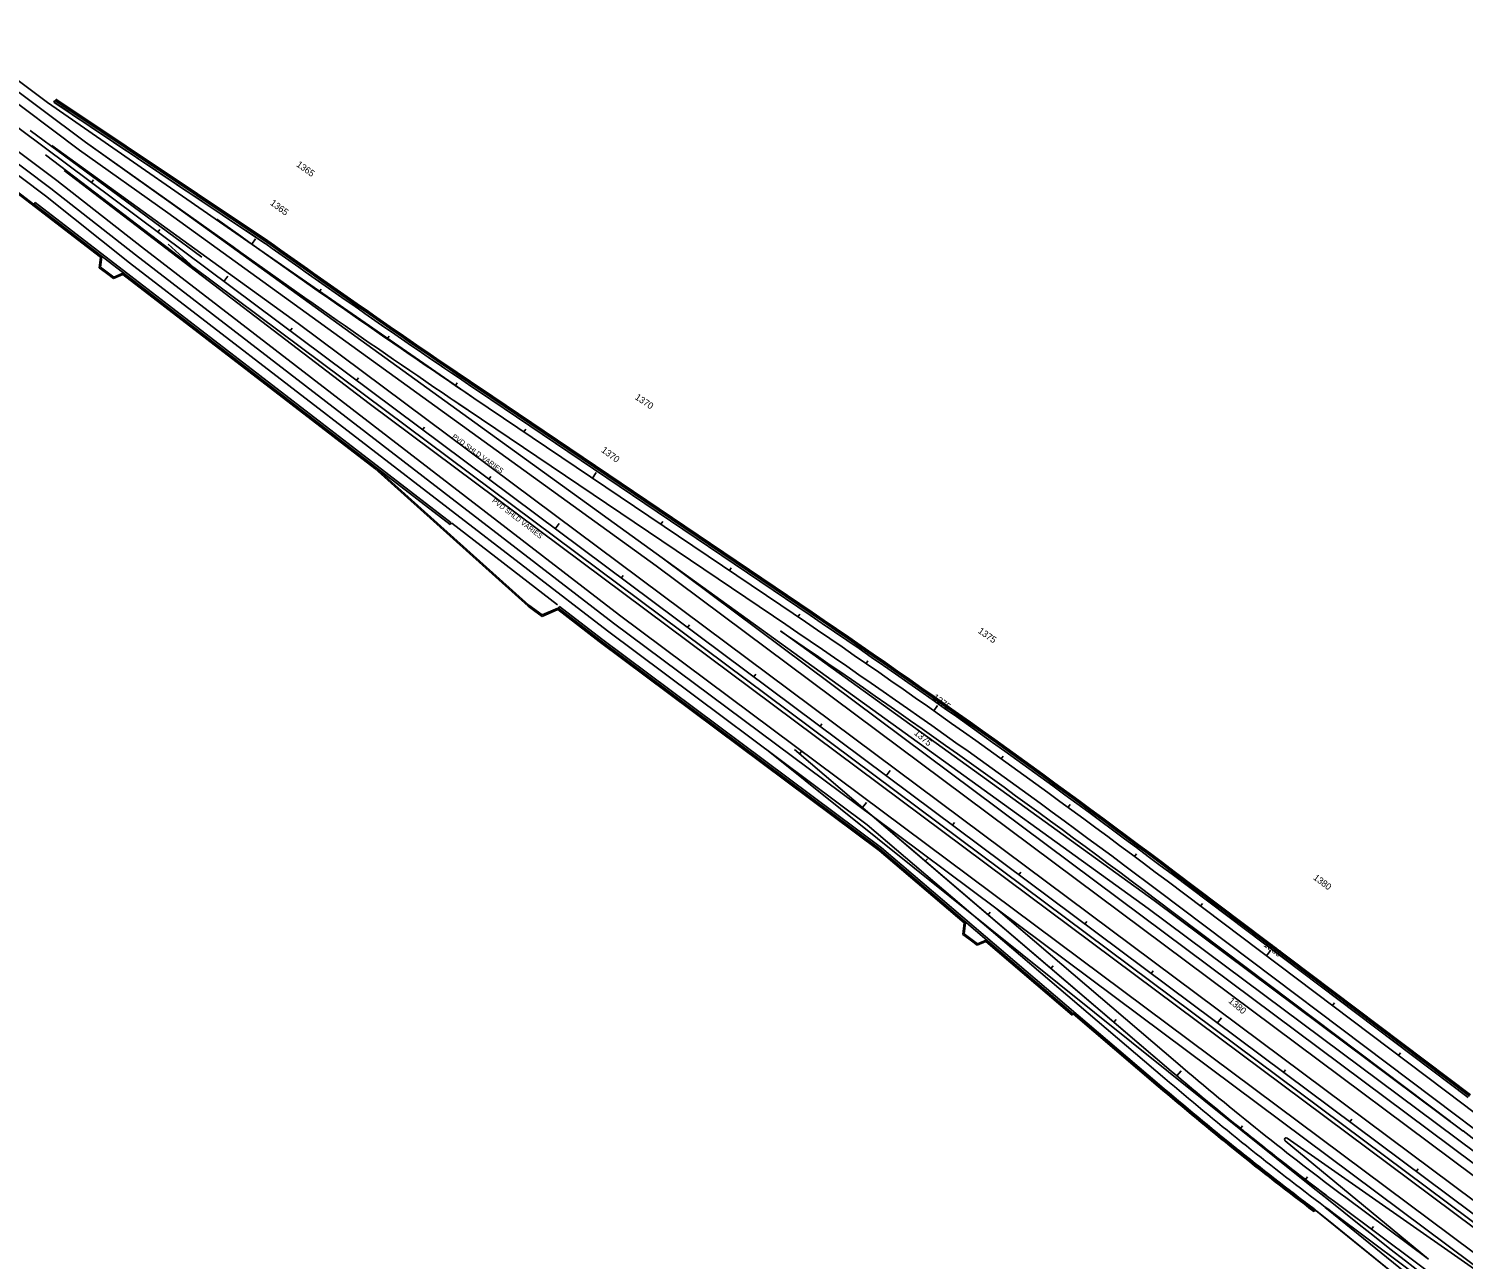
# Model space of a CAD drawing. Extents: x 2339272 to 2351734, y 366540 to 375057.
# Drawn here: x 2343436 to 2345172, y 370574 to 372063 of the extents above; entities that cross this region are included whole.
import ezdxf

# ---------------------------------------------------------------- set-up
doc = ezdxf.new("R2010")
doc.units = 0
for name, color, linetype in [('RD_HC_Cl', 7, 'Continuous'), ('RD_HC_CL_Rel', 7, 'Continuous'), ('RD_HC_Data_Tic', 7, 'Continuous'), ('RD_HC_Data_Tic_Rel', 7, 'Continuous'), ('RD_HC_TX_Rel_Sta50', 7, 'Continuous'), ('RD_HC_TX_Sta50', 7, 'Continuous'), ('RD_PD_Final_LnLine', 7, 'Continuous'), ('RD_PD_Final_TrvlWay', 7, 'Continuous'), ('RD_PD_GR', 7, 'Continuous'), ('RD_PD_GrRail', 7, 'Continuous'), ('RD_PD_MedBWall', 7, 'Continuous'), ('RD_PD_MedGR', 7, 'Continuous'), ('RD_PD_NOISE-WALL-GM', 7, 'Continuous'), ('RD_PD_PaveShd', 7, 'Continuous'), ('RD_PD_WallFill', 7, 'Continuous')]:
    doc.layers.add(name, color=color, linetype=linetype)

msp = doc.modelspace()

# ---------------------------------------------------------------- linework, layer by layer
at = {"layer": 'RD_HC_Cl'}
for p, q in [((2339299.7, 375020.3), (2345298.7, 370542.8)), ((2343974.3, 371616), (2344345.7, 371365.3)), ((2344813.1, 371031.8), (2345171.5, 370761.7))]:
    msp.add_line(p, q, dxfattribs=at)
for centre, radius, start, end in [((2351247.1, 382391.3), 13000, 234.31228, 235.98251), ((2338191.8, 362247.8), 11000, 52.99132, 55.9825), ((2352034, 379865.6), 11400.7, 232.99132, 241.72492)]:
    msp.add_arc(centre, radius, start, end, dxfattribs=at)
at = {"layer": 'RD_HC_CL_Rel'}
for p, q in [((2344362.1, 371190.8), (2344818.2, 370801.7)), ((2345022, 370639), (2345245.9, 370472))]:
    msp.add_line(p, q, dxfattribs=at)
msp.add_arc((2347422, 373854.7), 4012.5, 229.5396, 233.2637, dxfattribs=at)
at = {"layer": 'RD_HC_Data_Tic'}
for p, q in [((2343511.6, 371876.7), (2343514, 371879.9)), ((2343591.8, 371816.9), (2343594.2, 371820.1)), ((2343705.7, 371802.3), (2343710.3, 371808.8)), ((2343671.9, 371757.1), (2343676.7, 371763.5)), ((2343787.3, 371744.6), (2343789.6, 371747.9)), ((2343752, 371697.3), (2343754.4, 371700.5)), ((2343869.5, 371687.6), (2343871.7, 371690.9)), ((2343832.2, 371637.4), (2343834.6, 371640.6)), ((2343952, 371631.1), (2343954.3, 371634.4)), ((2343912.3, 371577.6), (2343914.7, 371580.8)), ((2344034.9, 371575.2), (2344037.1, 371578.5)), ((2343992.5, 371517.8), (2343994.8, 371521)), ((2344117.8, 371519.2), (2344122.2, 371525.8)), ((2344072.6, 371458), (2344077.4, 371464.4)), ((2344200.7, 371463.3), (2344202.9, 371466.6)), ((2344283.5, 371407.3), (2344285.8, 371410.6)), ((2344152.7, 371398.2), (2344155.1, 371401.4)), ((2344232.9, 371338.4), (2344235.3, 371341.6)), ((2344366.4, 371351.4), (2344368.7, 371354.7)), ((2344448.9, 371294.8), (2344451.2, 371298.1)), ((2344313, 371278.6), (2344315.4, 371281.8)), ((2344530.9, 371237.6), (2344535.5, 371244.1)), ((2344393.2, 371218.7), (2344395.5, 371222)), ((2344612.4, 371179.6), (2344614.7, 371182.8)), ((2344473.3, 371158.9), (2344478.1, 371165.3)), ((2344693.3, 371120.9), (2344695.7, 371124.1)), ((2344553.4, 371099.1), (2344555.8, 371102.3)), ((2344773.7, 371061.4), (2344776.1, 371064.6)), ((2344633.6, 371039.3), (2344636, 371042.5)), ((2344853.6, 371001.3), (2344856, 371004.5)), ((2344713.7, 370979.5), (2344716.1, 370982.7)), ((2344933.5, 370941.1), (2344938.3, 370947.5)), ((2344793.9, 370919.7), (2344796.2, 370922.9)), ((2345013.3, 370880.9), (2345015.7, 370884.1)), ((2344874, 370859.9), (2344878.8, 370866.3)), ((2345093.2, 370820.7), (2345095.6, 370823.9)), ((2344954.1, 370800.1), (2344956.5, 370803.3)), ((2345034.3, 370740.2), (2345036.7, 370743.4)), ((2345114.4, 370680.4), (2345116.8, 370683.6))]:
    msp.add_line(p, q, dxfattribs=at)
at = {"layer": 'RD_HC_Data_Tic_Rel'}
for p, q in [((2344368.3, 371185.5), (2344370.9, 371188.5)), ((2344444.4, 371120.6), (2344449.6, 371126.7)), ((2344520.5, 371055.7), (2344523.1, 371058.7)), ((2344596.6, 370990.8), (2344599.2, 370993.8)), ((2344672.6, 370925.9), (2344675.2, 370928.9)), ((2344748.7, 370861), (2344751.3, 370864.1)), ((2344824.8, 370796.1), (2344830, 370802.2)), ((2344901.8, 370732.4), (2344904.4, 370735.5)), ((2344980.4, 370670.5), (2344982.9, 370673.7)), ((2345060.4, 370610.4), (2345062.8, 370613.6))]:
    msp.add_line(p, q, dxfattribs=at)
at = {"layer": 'RD_PD_Final_LnLine'}
for p, q in [((2343497.3, 371916.1), (2339313.4, 375038.8)), ((2343504.5, 371925.7), (2339320.6, 375048.4)), ((2339278.7, 374992.3), (2343462.6, 371869.6)), ((2339285.9, 375001.9), (2343469.8, 371879.2)), ((2343497.3, 371916.1), (2343604.2, 371840)), ((2343469.8, 371879.2), (2343572.2, 371799)), ((2343462.6, 371869.6), (2343565, 371789.4)), ((2343604.2, 371840), (2344194.9, 371413.1)), ((2343572.2, 371799), (2344150.5, 371353.4)), ((2343565, 371789.4), (2344143.4, 371343.8)), ((2344195, 371413), (2345321, 370572.6)), ((2344202.2, 371422.6), (2344782.9, 370989.2)), ((2344143.4, 371343.8), (2344457.7, 371109.2)), ((2344150.5, 371353.5), (2345276.5, 370513.1)), ((2344330.6, 371189.3), (2344989.7, 370660.6)), ((2344330.6, 371189.3), (2344989.7, 370660.6)), ((2344330.6, 371189.3), (2344989.7, 370660.6)), ((2344330.6, 371189.3), (2344989.7, 370660.6)), ((2344457.7, 371109.2), (2344818.2, 370801.7)), ((2344457.7, 371109.2), (2344605.8, 370998.7)), ((2344782.9, 370989.2), (2345328.2, 370582.3)), ((2345014.9, 370629.4), (2345238.7, 370462.4)), ((2345022, 370639), (2345245.9, 370472))]:
    msp.add_line(p, q, dxfattribs=at)
for centre, radius, start, end in [((2347422, 373854.7), 4012.5, 229.5396, 232.9704), ((2351872.8, 379241), 11000, 231.26372, 239.17851), ((2351872.8, 379241), 11000, 231.26372, 239.17851), ((2351872.8, 379241), 11000, 231.26372, 239.17851), ((2351872.8, 379241), 11000, 231.26372, 239.17851), ((2347422, 373854.7), 4024.5, 232.9704, 233.2637)]:
    msp.add_arc(centre, radius, start, end, dxfattribs=at)
at = {"layer": 'RD_PD_Final_TrvlWay'}
for p, q in [((2343458.6, 371973.7), (2339327.2, 375057.2)), ((2339272.2, 374983.5), (2343456.1, 371860.8)), ((2343458.6, 371973.7), (2343725.7, 371788.1)), ((2343463.1, 371970.3), (2343462.9, 371970.4)), ((2343504.5, 371925.7), (2343504.5, 371925.7)), ((2343504.5, 371925.7), (2343610.9, 371850)), ((2343504.5, 371925.7), (2343654, 371819.6)), ((2343456.1, 371860.8), (2343557.8, 371779.8)), ((2343610.9, 371850), (2344202.2, 371422.6)), ((2343557.8, 371779.8), (2344136.2, 371334.2)), ((2343725.7, 371788.1), (2343974.3, 371616)), ((2343950.2, 371613), (2344336.8, 371352.1)), ((2343974.3, 371616), (2344345.7, 371365.3)), ((2344202.2, 371422.6), (2344790.4, 370998.6)), ((2344136.2, 371334.2), (2344450.2, 371099.8)), ((2344450.2, 371099.8), (2344810.5, 370792.6)), ((2344813.1, 371031.8), (2345171.5, 370761.7)), ((2344803.5, 371019), (2345161.9, 370748.9)), ((2344605.8, 370998.7), (2345269.3, 370503.4)), ((2344605.8, 370998.7), (2344826, 370810.9)), ((2344790.4, 370998.6), (2345335.3, 370591.9)), ((2344955.9, 370717.4), (2345129.3, 370574)), ((2345278, 370497), (2344958.3, 370720.6)), ((2345029.2, 370648.7), (2345129.3, 370574)), ((2345231.5, 370452.8), (2345014.5, 370628.6))]:
    msp.add_line(p, q, dxfattribs=at)
for centre, radius, start, end in [((2351247.1, 382391.3), 13016, 234.31228, 235.9825), ((2338191.8, 362247.8), 11000, 52.99132, 55.9825), ((2338191.8, 362247.8), 10984, 52.99132, 55.9825), ((2347422, 373854.7), 4000.5, 229.5396, 233.2637), ((2347422, 373854.7), 4024.5, 229.5396, 232.9704), ((2352034, 379865.6), 11400.7, 232.99132, 241.72492), ((2352034, 379865.6), 11416.7, 232.99132, 241.72492), ((2344957.1, 370719), 2, 53.2637, 231.8292), ((2347578.5, 373791.8), 4071.8, 230.6802, 230.9736)]:
    msp.add_arc(centre, radius, start, end, dxfattribs=at)
at = {"layer": 'RD_PD_GR'}
for p, q in [((2344075.4, 371365.9), (2343947.5, 371464.5)), ((2345225.2, 370445), (2345008.2, 370620.9))]:
    msp.add_line(p, q, dxfattribs=at)
msp.add_arc((2347578.5, 373791.8), 4081.8, 230.6802, 230.9736, dxfattribs=at)
at = {"layer": 'RD_PD_GrRail'}
for p, q in [((2343645.2, 371786.5), (2343437.5, 371939.8)), ((2343456.1, 371910.5), (2343635.6, 371773.5))]:
    msp.add_line(p, q, dxfattribs=at)
at = {"layer": 'RD_PD_MedBWall'}
for p, q in [((2343467.4, 371976.1), (2343466.1, 371974.2)), ((2343466.1, 371974.2), (2343721.1, 371803.5)), ((2343467.4, 371976.1), (2343723.9, 371804.5)), ((2343443.6, 371852.7), (2343442.2, 371850.8)), ((2343442.2, 371850.8), (2343945.5, 371463)), ((2343443.6, 371852.6), (2343946.9, 371464.9)), ((2343979.9, 371624.3), (2344351.3, 371373.6)), ((2343981.2, 371626.2), (2344352.6, 371375.6)), ((2343946.9, 371464.9), (2343945.5, 371463)), ((2344077.8, 371364), (2344076.4, 371362.2)), ((2344076.4, 371362.2), (2344127.3, 371323)), ((2344077.8, 371364), (2344128.7, 371324.8)), ((2344128.7, 371324.8), (2344467.4, 371072)), ((2344127.3, 371323), (2344466, 371070.2)), ((2344465.9, 371070.3), (2344699.6, 370870.9)), ((2344467.4, 371072), (2344804, 370785)), ((2344819.2, 371039.8), (2345177.5, 370769.6)), ((2344820.6, 371041.6), (2345178.9, 370771.5)), ((2344701.1, 370872.7), (2344699.6, 370870.9)), ((2344700.5, 370871.9), (2344803.3, 370784.2)), ((2344992.4, 370633.8), (2344991.8, 370633))]:
    msp.add_line(p, q, dxfattribs=at)
for centre, radius, start, end in [((2351247.1, 382391.3), 12990, 234.60122, 235.9825), ((2351247.1, 382391.3), 12987.7, 234.60122, 235.9825), ((2338191.8, 362247.8), 11012.3, 52.99132, 55.9825), ((2338191.8, 362247.8), 11010, 52.99132, 55.9825), ((2347422, 373854.7), 4035.5, 229.5396, 232.9704), ((2347422, 373854.7), 4034.5, 229.5396, 232.9704)]:
    msp.add_arc(centre, radius, start, end, dxfattribs=at)
at = {"layer": 'RD_PD_MedGR'}
for p, q in [((2343604.4, 371802.4), (2343635.7, 371774.1)), ((2343635.7, 371774.1), (2345204.8, 370603))]:
    msp.add_line(p, q, dxfattribs=at)
at = {"layer": 'RD_PD_NOISE-WALL-GM'}
for p, q in [((2343467.7, 371976.5), (2343724.1, 371804.9)), ((2343468.5, 371977.8), (2343725, 371806.2)), ((2343421.4, 371864.3), (2343522.5, 371786.4)), ((2343422.3, 371865.6), (2343524.1, 371787.1)), ((2343522.5, 371786.4), (2343521, 371773.7)), ((2343524.1, 371787.1), (2343522.6, 371774.4)), ((2343521, 371773.7), (2343529.7, 371767.2)), ((2343522.6, 371774.4), (2343530.6, 371768.4)), ((2343538.5, 371760.7), (2343529.7, 371767.2)), ((2343538.7, 371762.5), (2343530.6, 371768.4)), ((2343549.6, 371765.5), (2343538.5, 371760.7)), ((2343549.8, 371767.3), (2343538.7, 371762.5)), ((2343549.6, 371765.5), (2343854.4, 371530.7)), ((2343549.8, 371767.3), (2343855.3, 371531.9)), ((2343981.5, 371626.7), (2344352.9, 371376)), ((2343982.4, 371627.9), (2344353.8, 371377.2)), ((2343855.3, 371531.9), (2344041, 371365.5)), ((2343854.4, 371530.7), (2344040.1, 371364.4)), ((2344040.1, 371364.4), (2344048.1, 371358.3)), ((2344041, 371365.5), (2344057, 371353.6)), ((2344056.8, 371351.8), (2344048.1, 371358.3)), ((2344075.9, 371360), (2344056.8, 371351.8)), ((2344076.1, 371361.8), (2344057, 371353.6)), ((2344075.9, 371360), (2344126.1, 371321.4)), ((2344076.1, 371361.8), (2344127, 371322.6)), ((2344126.1, 371321.4), (2344464.7, 371068.6)), ((2344127, 371322.6), (2344465.6, 371069.8)), ((2344464.7, 371068.6), (2344567.6, 370980.9)), ((2344465.6, 371069.8), (2344569.2, 370981.5)), ((2344820.9, 371042), (2345179.2, 370771.9)), ((2344821.8, 371043.2), (2345180.1, 370773.1)), ((2344567.6, 370980.9), (2344566, 370966.9)), ((2344569.2, 370981.5), (2344567.5, 370967.6)), ((2344566, 370966.9), (2344574.7, 370960.4)), ((2344567.5, 370967.6), (2344575.6, 370961.6)), ((2344583.4, 370953.9), (2344574.7, 370960.4)), ((2344583.6, 370955.6), (2344575.6, 370961.6)), ((2344594.2, 370960.2), (2344583.6, 370955.6)), ((2344594.2, 370960.2), (2344699.3, 370870.6)), ((2344593.9, 370958.4), (2344583.4, 370953.9)), ((2344593.9, 370958.4), (2344698.3, 370869.4)), ((2344699.3, 370870.6), (2344698.3, 370869.4))]:
    msp.add_line(p, q, dxfattribs=at)
for centre, radius, start, end in [((2351247.1, 382391.3), 12987.2, 234.60122, 235.9825), ((2351247.1, 382391.3), 12985.7, 234.60122, 235.9825), ((2338191.8, 362247.8), 11012.8, 52.99132, 55.9825), ((2338191.8, 362247.8), 11014.3, 52.99132, 55.9825)]:
    msp.add_arc(centre, radius, start, end, dxfattribs=at)
at = {"layer": 'RD_PD_PaveShd'}
for p, q in [((2343463.9, 371921.7), (2343761.9, 371706.3)), ((2343478.6, 371891.2), (2343847.6, 371609.5)), ((2343761.9, 371706.3), (2345306.6, 370553.4)), ((2343979.9, 371624.3), (2344351.3, 371373.6)), ((2343847.6, 371609.5), (2345290.9, 370532.3)), ((2344128.8, 371324.8), (2344467.4, 371072)), ((2344345.4, 371334.2), (2344797.5, 371008.3)), ((2344467.4, 371072), (2344804, 370785)), ((2344819.2, 371039.8), (2345177.5, 370769.6)), ((2344797.5, 371011), (2345155.9, 370740.9)), ((2344797.5, 371008.3), (2345171.3, 370729.2)), ((2345225.4, 370444.9), (2344991, 370634.8))]:
    msp.add_line(p, q, dxfattribs=at)
for centre, radius, start, end in [((2378085.8, 423428.9), 62017, 236.066595, 236.351585), ((2351247.1, 382391.3), 12990, 234.60122, 235.9825), ((2338191.8, 362247.8), 11010, 52.99132, 55.9825), ((2338191.8, 362247.8), 10974, 52.99132, 55.89285), ((2347422, 373854.7), 4034.5, 229.5396, 232.9458), ((2352034, 379865.6), 11426.7, 233.08852, 240.43661)]:
    msp.add_arc(centre, radius, start, end, dxfattribs=at)
at = {"layer": 'RD_PD_WallFill'}
for p, q in [((2344699.5, 370870.8), (2344802.3, 370783.1)), ((2344699.8, 370871.2), (2344802.7, 370783.5)), ((2344700.1, 370871.6), (2344803, 370783.8)), ((2344700.5, 370871.9), (2344803.3, 370784.2)), ((2344991.8, 370633), (2344990.9, 370631.8))]:
    msp.add_line(p, q, dxfattribs=at)
for radius in [4037, 4036.5, 4036]:
    msp.add_arc((2347422, 373854.7), radius, 229.5396, 232.9704, dxfattribs=at)

# ---------------------------------------------------------------- texts
at = {"layer": 'RD_HC_TX_Rel_Sta50'}
for s, rotation, p in [('1375', 319.5396, (2344506.3, 371209.7)), ('1380', 319.6629, (2344886.6, 370885.4))]:
    msp.add_text(s, height=8, rotation=rotation, dxfattribs=at).set_placement(p)
at = {"layer": 'RD_HC_TX_Sta50'}
for s, rotation, p in [('1365', 324.5415, (2343758.8, 371897)), ('1365', 323.2637, (2343727.2, 371850.6)), ('1370', 325.9825, (2344168.5, 371615.3)), ('1370', 323.2637, (2344127.8, 371551.5)), ('1375', 324.8108, (2344583.6, 371332.6)), ('1375', 323.2637, (2344528.6, 371252.4)), ('1380', 322.9913, (2344989.2, 371034.4)), ('1380', 323.2637, (2344929.2, 370953.4))]:
    msp.add_text(s, height=8, rotation=rotation, dxfattribs=at).set_placement(p)
at = {"layer": 'RD_PD_Final_TrvlWay'}
for rotation, p in [(324.1408, (2343947.4, 371568.2)), (322.3866, (2343995.8, 371490.7))]:
    msp.add_text('PVD SHLD VARIES', height=6, rotation=rotation, dxfattribs=at).set_placement(p)

doc.saveas('drawing.dxf')
